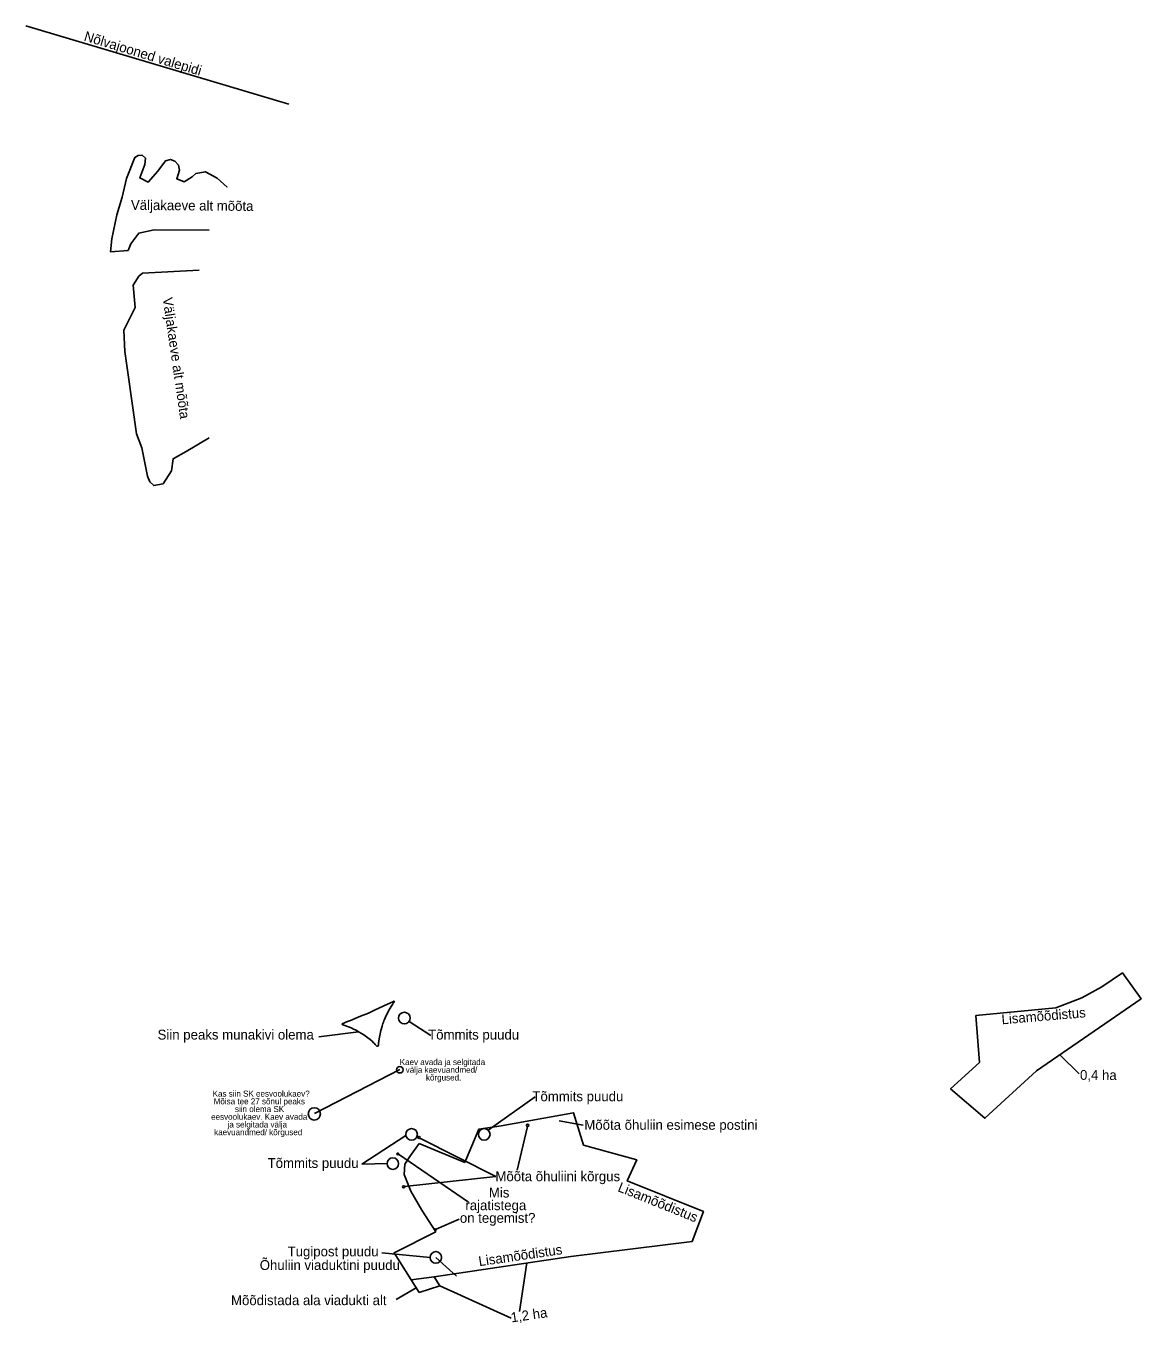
# Model space of a CAD drawing. Extents: x 577813 to 578499, y 6590506 to 6591304.
import ezdxf

# ---------------------------------------------------------------- set-up
doc = ezdxf.new("R2010")
doc.units = 0
doc.layers.add('Lisamõõdistus', color=7, linetype='Continuous')
doc.layers.add('Märkused', color=7, linetype='Continuous')

msp = doc.modelspace()

# ---------------------------------------------------------------- linework, layer by layer
at = {"layer": 'Lisamõõdistus'}
for p, q in [((578461.34, 6590659.31), (578449.33, 6590671)), ((578083.32, 6590604.77), (578055.15, 6590616.42)), ((578121.47, 6590542.81), (578117, 6590512.95)), ((578067.87, 6590528.76), (578111.77, 6590508.82)), ((578053.26, 6590527.5), (578041, 6590520.42))]:
    msp.add_line(p, q, dxfattribs=at)
for points in [[(578397.66, 6590695.18), (578399.91, 6590666.34), (578382.15, 6590650.14), (578403.3, 6590631.89), (578435.02, 6590661.14), (578499.39, 6590705.51), (578487.89, 6590721.43), (578475.22, 6590712.81), (578462.89, 6590706.06), (578446.97, 6590699.83), (578397.66, 6590695.18)], [(578148.45, 6590546.81), (578223.17, 6590555.97), (578230.05, 6590574.45), (578183.24, 6590593.36), (578189.03, 6590606.31), (578156.4, 6590615.45), (578150.23, 6590635.35), (578105.54, 6590627.18), (578091.92, 6590625.26), (578083.32, 6590604.77)], [(578055.15, 6590616.42), (578049.43, 6590608.44), (578046.41, 6590603.67), (578045.89, 6590597.27), (578050.08, 6590587.04), (578056.73, 6590575.43), (578065.47, 6590562.08)], [(578065.47, 6590562.08), (578039.79, 6590549.07), (578050.19, 6590532.42)], [(578050.19, 6590532.42), (578064.34, 6590534.35), (578148.45, 6590546.81)]]:
    msp.add_lwpolyline(points, dxfattribs=at)
msp.add_lwpolyline([(578055.09, 6590524.58), (578067.87, 6590528.76), (578064.34, 6590534.35), (578050.19, 6590532.42)], close=True, dxfattribs=at)
at = {"layer": 'Märkused'}
for p, q in [((577813.22, 6591304.47), (577974.99, 6591256.4)), ((578048.99, 6590691.59), (578062.43, 6590682.93)), ((577993.51, 6590682.12), (578017.94, 6590685.22)), ((577990.82, 6590634.94), (578043.19, 6590661.97)), ((578097.74, 6590624.55), (578126.5, 6590645.15)), ((578115.53, 6590599.98), (578121.9, 6590626.88)), ((578141.29, 6590630.28), (578156.16, 6590627.77)), ((578019.99, 6590603.64), (578047.08, 6590621.22)), ((578102.43, 6590596.09), (578055.6, 6590619.6)), ((578042.52, 6590609.82), (578085.49, 6590580.36)), ((578019.99, 6590603.64), (578035.41, 6590603.98)), ((578046.25, 6590589.86), (578102.43, 6590596.09)), ((578065.6, 6590563.62), (578079.78, 6590569.76)), ((578032.12, 6590549.06), (578061.87, 6590546.22)), ((578065.45, 6590546.28), (578078.19, 6590534.72))]:
    msp.add_line(p, q, dxfattribs=at)
for points in [[(577925.91, 6591178.67), (577892.21, 6591178.85), (577882.67, 6591176.85), (577877.83, 6591170.3), (577876.03, 6591166.3), (577865.2, 6591165.39), (577866.07, 6591173.47), (577869.11, 6591188.13), (577872.38, 6591198.95), (577875.14, 6591210.55), (577880.12, 6591223.49), (577882.31, 6591224.75), (577884.68, 6591225), (577886.78, 6591222.96), (577886.44, 6591219.14), (577883.23, 6591210.91), (577888.45, 6591208.31), (577894.36, 6591215.05), (577899.13, 6591221.34), (577902.11, 6591222.26), (577904.77, 6591221.28), (577907.11, 6591218.83), (577907.78, 6591215.62), (577906.02, 6591210.42), (577910.64, 6591208.42), (577915.57, 6591211.64), (577917.68, 6591213.56), (577923.64, 6591214.67), (577930.96, 6591210.71), (577937.02, 6591205.25), (577937.02, 6591205.25)], [(577888.02, 6591027.33), (577884.53, 6591044.78), (577881.19, 6591053.33), (577876.07, 6591089.68), (577874.04, 6591103.95), (577873.35, 6591117.12), (577880.49, 6591131.09), (577879.15, 6591144.91), (577882.67, 6591150.31), (577884.85, 6591152.17), (577919.71, 6591154.08)], [(577925.86, 6591050.84), (577911.73, 6591042.38), (577903.8, 6591037.94), (577902.76, 6591030.54), (577897.6, 6591022.56), (577891.82, 6591021.42), (577889.48, 6591023.82), (577888.02, 6591027.33)], [(578029.01, 6590676.54), (578029.16, 6590676.38), (578029.22, 6590676.34), (578029.3, 6590676.32), (578029.5, 6590676.3), (578029.71, 6590676.3), (578029.88, 6590676.33), (578029.95, 6590676.4), (578030.03, 6590676.5), (578030.09, 6590676.67), (578030.24, 6590677.95), (578030.43, 6590679.43), (578030.61, 6590680.9), (578030.92, 6590682.95), (578031.11, 6590683.98), (578031.35, 6590685.02), (578031.61, 6590685.97), (578031.93, 6590687.16), (578032.4, 6590688.68), (578032.91, 6590690.25), (578033.22, 6590691.07), (578033.52, 6590691.96), (578033.87, 6590692.71), (578034.3, 6590693.77), (578035.18, 6590695.62), (578035.66, 6590696.61), (578036.34, 6590697.99), (578037.28, 6590699.72), (578037.87, 6590700.66), (578038.79, 6590702.06), (578039.25, 6590702.71), (578039.62, 6590703.23), (578039.86, 6590703.58), (578039.9, 6590703.73), (578039.87, 6590703.88), (578039.78, 6590704.01), (578039.63, 6590704), (578039, 6590703.7), (578037.51, 6590702.99), (578033.51, 6590701.11), (578027.73, 6590698.4), (578023.99, 6590696.69), (578020.78, 6590695.39), (578018.08, 6590694.28), (578013.94, 6590692.6), (578010.11, 6590691.06), (578008.34, 6590690.36), (578007.96, 6590690.18), (578007.83, 6590690.05), (578007.81, 6590689.99), (578007.82, 6590689.85), (578007.84, 6590689.73), (578007.86, 6590689.68), (578007.95, 6590689.58), (578008.03, 6590689.52), (578008.87, 6590689.2), (578009.52, 6590688.97), (578011.09, 6590688.35), (578012.24, 6590687.92), (578013.72, 6590687.33), (578014.8, 6590686.85), (578015.92, 6590686.27), (578017.01, 6590685.71), (578017.94, 6590685.22), (578018.73, 6590684.79), (578019.39, 6590684.39), (578020.12, 6590683.94), (578021.14, 6590683.26), (578022.04, 6590682.65), (578022.78, 6590682.09), (578023.62, 6590681.45), (578025.02, 6590680.33), (578026.21, 6590679.29), (578027.13, 6590678.42), (578027.42, 6590678.17), (578028.18, 6590677.41), (578028.82, 6590676.74), (578029.01, 6590676.54)]]:
    msp.add_lwpolyline(points, dxfattribs=at)
for centre, radius in [((578046.06, 6590693.62), 3.57), ((578043.3, 6590661.79), 1.98), ((577990.67, 6590634.63), 3.78), ((578050.56, 6590622.02), 3.57), ((578095.21, 6590622.02), 3.57), ((578121.9, 6590627.57), 0.692), ((578055.12, 6590620.1), 0.692), ((578042.02, 6590609.98), 0.529), ((578038.99, 6590603.98), 3.57), ((578045.58, 6590589.7), 0.692), ((578065.11, 6590563.34), 0.555), ((578065.44, 6590546.22), 3.57)]:
    msp.add_circle(centre, radius, dxfattribs=at)

# ---------------------------------------------------------------- texts
at = {"layer": 'Lisamõõdistus'}
for s, height, rotation, p in [('Lisamõõdistus', 6.0736, 4.83327, (578413.8, 6590689.75)), ('0,4 ha ', 6.074, 359.67797, (578461.82, 6590655.57)), ('Lisamõõdistus', 6.0736, 338.02956, (578176.93, 6590587.16)), ('Lisamõõdistus', 6.0736, 8.26382, (578092.18, 6590540.81)), ('1,2 ha', 6.074, 8.26382, (578112.04, 6590506.2))]:
    msp.add_text(s, height=height, rotation=rotation, dxfattribs=at).set_placement(p)
msp.add_text('Mõõdistada ala viadukti alt', height=6.0736, dxfattribs=at).set_placement((577939.41, 6590516.86))
at = {"layer": 'Märkused'}
for s, rotation, p in [('Nõlvajooned valepidi', 343.12301, (577848.5, 6591295.55)), ('Väljakaeve alt mõõta', 359.46309, (577877.79, 6591191.24)), ('Väljakaeve alt mõõta', 278.28269, (577897.31, 6591136.85))]:
    msp.add_text(s, height=6.0736, rotation=rotation, dxfattribs=at).set_placement(p)
for s, height, p in [('Siin peaks munakivi olema', 6.0736, (577894.22, 6590680.39)), ('Tõmmits puudu', 6.0736, (578060.71, 6590680.4)), ('Kaev avada ja selgitada ', 3.7027, (578043.22, 6590664.67)), ('välja kaevuandmed/ ', 3.7027, (578046.91, 6590659.92)), ('kõrgused.', 3.703, (578059.36, 6590655.17)), ('Kas siin SK eesvoolukaev?', 3.7027, (577928.09, 6590645.24)), ('Tõmmits puudu', 6.0736, (578124.86, 6590642.4)), ('Mõisa tee 27 sõnul peaks ', 3.7027, (577928.74, 6590640.49)), ('siin olema SK ', 3.7027, (577941.82, 6590635.74)), ('eesvoolukaev. Kaev avada ', 3.7027, (577927.16, 6590630.99)), ('kaevuandmed/ kõrgused', 3.7027, (577929.04, 6590621.49)), ('ja selgitada välja ', 3.7027, (577937.27, 6590626.24)), ('Mõõta õhuliin esimese postini', 6.0736, (578156.82, 6590624.84)), ('Tõmmits puudu', 6.0736, (577961.93, 6590601.32)), ('Mõõta õhuliini kõrgus', 6.0736, (578102.1, 6590593.16)), ('Mis ', 6.074, (578098.07, 6590583.14)), ('rajatistega ', 6.0736, (578083.6, 6590575.35)), ('on tegemist?', 6.0736, (578080.23, 6590567.55)), ('Tugipost puudu', 6.0736, (577974.22, 6590546.89)), ('Õhuliin viaduktini puudu', 6.0736, (577957.08, 6590538.51))]:
    msp.add_text(s, height=height, dxfattribs=at).set_placement(p)

doc.saveas('drawing.dxf')
